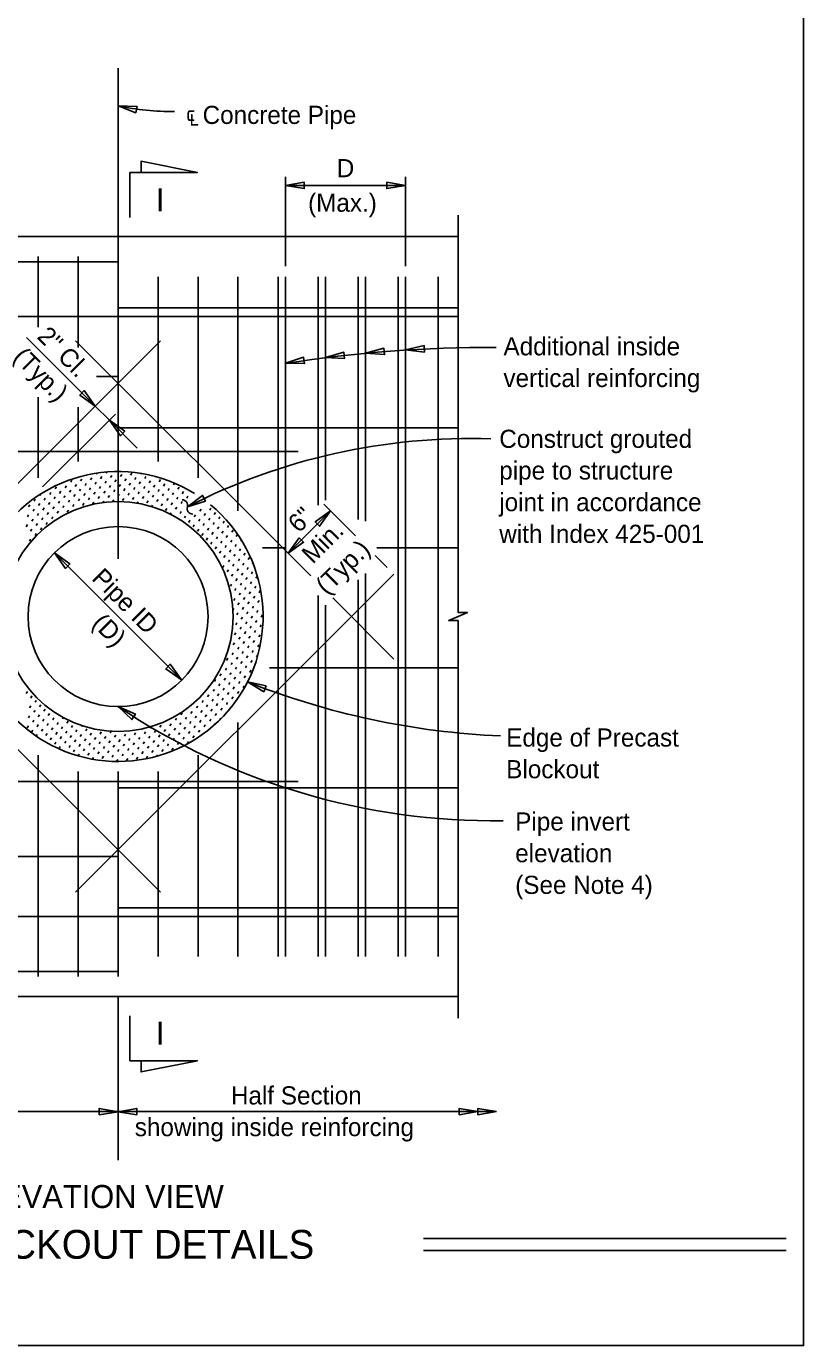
# Model space of a CAD drawing. Extents: x 0 to 30.8, y 0 to 19.8.
# Drawn here: x 24.32 to 30.8, y 0 to 11 of the extents above; entities that cross this region are included whole.
import ezdxf

# ---------------------------------------------------------------- set-up
doc = ezdxf.new("R2010")
doc.units = 0
for name, color, linetype in [('CL_Major', 7, 'Continuous'), ('Dimension', 7, 'Continuous'), ('Miscellaneous', 7, 'Continuous'), ('Miscellaneous1', 7, 'Continuous'), ('Rebar', 7, 'Continuous'), ('SubStrConc', 7, 'Continuous'), ('SubStrConc_h', 7, 'Continuous'), ('TextStructures', 7, 'Continuous')]:
    doc.layers.add(name, color=color, linetype=linetype)

msp = doc.modelspace()

# ---------------------------------------------------------------- linework, layer by layer
at = {"layer": 'CL_Major'}
for p, q in [((25.088, 10.648), (25.088, 6.558)), ((25.088, 4.785), (25.088, 4.383)), ((25.088, 1.547), (25.088, 2.91))]:
    msp.add_line(p, q, dxfattribs=at)
at = {"layer": 'Dimension'}
for p, q in [((25.749, 9.779), (25.28, 9.872)), ((25.28, 9.872), (25.28, 9.779)), ((25.186, 9.404), (25.186, 9.779)), ((25.186, 9.779), (25.749, 9.779)), ((26.483, 8.997), (26.483, 9.743)), ((27.483, 8.997), (27.483, 9.743)), ((26.483, 9.671), (27.483, 9.671)), ((24.324, 8.404), (24.897, 7.831)), ((25.015, 7.713), (24.897, 7.831)), ((24.459, 7.157), (25.067, 7.765)), ((25.015, 7.713), (25.248, 7.48)), ((26.858, 6.958), (26.505, 6.604)), ((27.065, 6.751), (26.801, 7.015)), ((25.615, 5.55), (24.557, 6.607)), ((27.329, 6.487), (27.23, 6.587)), ((25.186, 2.75), (25.186, 2.375)), ((25.186, 2.375), (25.749, 2.375)), ((25.749, 2.375), (25.28, 2.282)), ((25.28, 2.282), (25.28, 2.375)), ((25.088, 1.951), (21.845, 1.951)), ((25.088, 1.951), (28.242, 1.951)), ((30.655, 0.894), (27.633, 0.894)), ((30.655, 0.794), (27.633, 0.794))]:
    msp.add_line(p, q, dxfattribs=at)
for points in [[(25.088, 10.334), (25.235, 10.276), (25.246, 10.328)], [(25.28, 9.779), (25.28, 9.872), (25.749, 9.779)], [(26.483, 9.671), (26.639, 9.644), (26.639, 9.697)], [(27.483, 9.671), (27.327, 9.697), (27.327, 9.644)], [(26.817, 8.235), (26.968, 8.281), (26.975, 8.229)], [(27.15, 8.272), (27.303, 8.313), (27.308, 8.261)], [(27.483, 8.299), (27.637, 8.335), (27.641, 8.282)], [(26.483, 8.188), (26.633, 8.239), (26.642, 8.186)], [(24.897, 7.831), (24.806, 7.96), (24.768, 7.923)], [(25.015, 7.713), (25.107, 7.584), (25.144, 7.622)], [(25.665, 6.991), (25.816, 7.039), (25.792, 7.086)], [(26.858, 6.958), (26.729, 6.866), (26.767, 6.829)], [(26.505, 6.604), (26.634, 6.696), (26.597, 6.733)], [(24.557, 6.607), (24.649, 6.478), (24.686, 6.516)], [(25.615, 5.55), (25.523, 5.679), (25.486, 5.641)], [(26.166, 5.532), (26.301, 5.45), (26.321, 5.499)], [(25.088, 5.327), (25.203, 5.218), (25.232, 5.262)], [(25.28, 2.375), (25.28, 2.282), (25.749, 2.375)], [(25.088, 1.95), (24.931, 1.977), (24.931, 1.924)], [(25.088, 1.95), (25.244, 1.924), (25.244, 1.977)], [(28.086, 1.951), (27.93, 1.977), (27.93, 1.924)], [(28.242, 1.951), (28.086, 1.977), (28.086, 1.924)]]:
    msp.add_lwpolyline(points, close=True, dxfattribs=at)
msp.add_lwpolyline([(27.921, 2.73), (27.921, 6.043), (27.843, 6.043), (27.921, 6.077), (27.998, 6.111), (27.921, 6.111), (27.921, 9.424)], dxfattribs=at)
for centre, radius, start, end in [((25.551, 12.543), 2.257, 258.1436, 270.1956), ((28.171, -2.483), 10.803, 89.6404, 98.9861), ((28.024, 2.388), 5.173, 88.1103, 117.1325), ((25.623, 7.005), 0.0447, 341.3118, 93.039), ((25.708, 6.976), 0.0447, 161.3118, 273.039), ((28.551, 11.535), 6.459, 248.3277, 267.5443), ((28.22, 10.004), 5.63, 236.1859, 270.7687)]:
    msp.add_arc(centre, radius, start, end, dxfattribs=at)
at = {"layer": 'Miscellaneous'}
for p, q in [((24.906, 7.263), (24.911, 7.272)), ((24.989, 7.272), (24.994, 7.281)), ((25.072, 7.282), (25.073, 7.285)), ((25.108, 7.245), (25.118, 7.262)), ((25.191, 7.255), (25.201, 7.272)), ((25.274, 7.265), (25.277, 7.27)), ((24.564, 7.141), (24.574, 7.158)), ((24.647, 7.151), (24.657, 7.167)), ((24.693, 7.197), (24.703, 7.214)), ((24.73, 7.16), (24.74, 7.177)), ((24.776, 7.207), (24.786, 7.223)), ((24.813, 7.17), (24.823, 7.187)), ((24.823, 7.253), (24.824, 7.256)), ((24.849, 7.133), (24.859, 7.15)), ((24.859, 7.216), (24.869, 7.233)), ((24.896, 7.18), (24.906, 7.196)), ((24.932, 7.143), (24.942, 7.16)), ((24.942, 7.226), (24.952, 7.243)), ((24.979, 7.189), (24.989, 7.206)), ((25.015, 7.153), (25.025, 7.17)), ((25.025, 7.236), (25.035, 7.253)), ((25.062, 7.199), (25.072, 7.216)), ((25.098, 7.162), (25.108, 7.179)), ((25.145, 7.209), (25.154, 7.226)), ((25.181, 7.172), (25.191, 7.189)), ((25.218, 7.136), (25.228, 7.152)), ((25.228, 7.219), (25.237, 7.235)), ((25.264, 7.182), (25.274, 7.199)), ((25.301, 7.145), (25.311, 7.162)), ((25.311, 7.228), (25.32, 7.245)), ((25.347, 7.192), (25.357, 7.208)), ((25.384, 7.155), (25.394, 7.172)), ((25.394, 7.238), (25.398, 7.245)), ((25.43, 7.201), (25.44, 7.218)), ((25.467, 7.165), (25.477, 7.182)), ((25.55, 7.174), (25.559, 7.19)), ((25.587, 7.138), (25.596, 7.155)), ((24.388, 7.038), (24.398, 7.055)), ((24.435, 7.085), (24.443, 7.099)), ((24.471, 7.048), (24.481, 7.065)), ((24.518, 7.094), (24.527, 7.111)), ((24.554, 7.058), (24.564, 7.075)), ((24.591, 7.021), (24.601, 7.038)), ((24.601, 7.104), (24.61, 7.121)), ((24.637, 7.068), (24.647, 7.084)), ((24.674, 7.031), (24.684, 7.048)), ((24.684, 7.114), (24.693, 7.131)), ((24.72, 7.077), (24.73, 7.094)), ((24.757, 7.041), (24.767, 7.057)), ((24.767, 7.124), (24.776, 7.14)), ((24.803, 7.087), (24.813, 7.104)), ((24.84, 7.05), (24.849, 7.067)), ((24.886, 7.097), (24.896, 7.113)), ((24.923, 7.06), (24.932, 7.077)), ((24.961, 7.026), (24.969, 7.04)), ((24.969, 7.106), (24.979, 7.123)), ((25.006, 7.07), (25.015, 7.087)), ((25.042, 7.033), (25.052, 7.05)), ((25.052, 7.116), (25.062, 7.133)), ((25.089, 7.08), (25.098, 7.096)), ((25.125, 7.043), (25.135, 7.06)), ((25.135, 7.126), (25.145, 7.143)), ((25.172, 7.089), (25.181, 7.106)), ((25.208, 7.053), (25.218, 7.069)), ((25.255, 7.099), (25.264, 7.116)), ((25.291, 7.062), (25.301, 7.079)), ((25.328, 7.026), (25.338, 7.042)), ((25.338, 7.109), (25.347, 7.125)), ((25.374, 7.072), (25.384, 7.089)), ((25.411, 7.035), (25.421, 7.052)), ((25.421, 7.118), (25.43, 7.135)), ((25.457, 7.082), (25.467, 7.099)), ((25.494, 7.045), (25.504, 7.062)), ((25.504, 7.128), (25.513, 7.145)), ((25.54, 7.091), (25.55, 7.108)), ((25.577, 7.055), (25.587, 7.072)), ((25.623, 7.101), (25.633, 7.118)), ((25.66, 7.065), (25.67, 7.081)), ((25.706, 7.111), (25.708, 7.114)), ((24.342, 6.992), (24.352, 7.009)), ((24.379, 6.955), (24.388, 6.972)), ((24.415, 6.919), (24.425, 6.936)), ((24.425, 7.002), (24.435, 7.019)), ((24.461, 6.965), (24.471, 6.982)), ((24.498, 6.928), (24.508, 6.945)), ((24.508, 7.011), (24.518, 7.028)), ((24.544, 6.975), (24.554, 6.992)), ((24.581, 6.938), (24.591, 6.955)), ((24.627, 6.985), (24.637, 7.001)), ((24.664, 6.948), (24.674, 6.965)), ((24.71, 6.994), (24.72, 7.011)), ((24.793, 7.004), (24.803, 7.021)), ((24.876, 7.014), (24.886, 7.031)), ((25.248, 7.021), (25.255, 7.033)), ((25.367, 6.993), (25.374, 7.006)), ((25.448, 6.999), (25.457, 7.016)), ((25.484, 6.962), (25.494, 6.979)), ((25.523, 6.929), (25.531, 6.942)), ((25.531, 7.009), (25.54, 7.025)), ((25.567, 6.972), (25.577, 6.989)), ((25.604, 6.935), (25.613, 6.952)), ((25.613, 7.018), (25.623, 7.035)), ((25.77, 6.955), (25.779, 6.972)), ((25.806, 6.918), (25.816, 6.935)), ((25.853, 6.964), (25.862, 6.981)), ((25.889, 6.928), (25.899, 6.945)), ((24.322, 6.826), (24.332, 6.843)), ((24.332, 6.909), (24.342, 6.926)), ((24.369, 6.872), (24.379, 6.889)), ((24.405, 6.836), (24.415, 6.853)), ((24.452, 6.882), (24.461, 6.899)), ((24.488, 6.845), (24.498, 6.862)), ((24.535, 6.892), (24.544, 6.909)), ((24.626, 6.916), (24.627, 6.918)), ((25.64, 6.899), (25.65, 6.915)), ((25.677, 6.862), (25.687, 6.879)), ((25.714, 6.825), (25.723, 6.842)), ((25.723, 6.908), (25.733, 6.925)), ((25.76, 6.872), (25.77, 6.889)), ((25.797, 6.835), (25.806, 6.852)), ((25.843, 6.881), (25.853, 6.898)), ((25.88, 6.845), (25.889, 6.862)), ((25.916, 6.808), (25.926, 6.825)), ((25.926, 6.891), (25.936, 6.908)), ((25.963, 6.855), (25.972, 6.871)), ((25.999, 6.818), (26.009, 6.835)), ((24.349, 6.706), (24.359, 6.723)), ((24.359, 6.789), (24.369, 6.806)), ((24.396, 6.753), (24.405, 6.77)), ((24.442, 6.799), (24.452, 6.816)), ((25.75, 6.789), (25.76, 6.806)), ((25.787, 6.752), (25.797, 6.769)), ((25.824, 6.715), (25.833, 6.732)), ((25.833, 6.798), (25.843, 6.815)), ((25.87, 6.762), (25.88, 6.779)), ((25.907, 6.725), (25.916, 6.742)), ((25.953, 6.772), (25.963, 6.788)), ((25.989, 6.735), (25.999, 6.752)), ((26.026, 6.698), (26.036, 6.715)), ((26.036, 6.781), (26.046, 6.798)), ((26.072, 6.745), (26.082, 6.761)), ((26.109, 6.708), (26.113, 6.715)), ((25.86, 6.679), (25.87, 6.696)), ((25.897, 6.642), (25.907, 6.659)), ((25.933, 6.606), (25.943, 6.622)), ((25.943, 6.689), (25.953, 6.705)), ((25.98, 6.652), (25.989, 6.669)), ((26.016, 6.615), (26.026, 6.632)), ((26.063, 6.662), (26.072, 6.678)), ((26.099, 6.625), (26.109, 6.642)), ((26.136, 6.588), (26.146, 6.605)), ((25.929, 6.533), (25.933, 6.539)), ((25.96, 6.486), (25.97, 6.503)), ((25.97, 6.569), (25.98, 6.586)), ((26.007, 6.532), (26.016, 6.549)), ((26.043, 6.496), (26.053, 6.513)), ((26.053, 6.579), (26.063, 6.595)), ((26.09, 6.542), (26.099, 6.559)), ((26.126, 6.505), (26.136, 6.522)), ((26.173, 6.552), (26.182, 6.569)), ((26.209, 6.515), (26.212, 6.519)), ((25.996, 6.381), (25.997, 6.383)), ((25.997, 6.449), (26.007, 6.466)), ((26.034, 6.413), (26.043, 6.43)), ((26.07, 6.376), (26.08, 6.393)), ((26.08, 6.459), (26.09, 6.476)), ((26.117, 6.422), (26.126, 6.439)), ((26.153, 6.386), (26.163, 6.403)), ((26.163, 6.469), (26.173, 6.486)), ((26.2, 6.432), (26.209, 6.449)), ((26.236, 6.396), (26.246, 6.412)), ((26.024, 6.33), (26.034, 6.347)), ((26.06, 6.293), (26.07, 6.31)), ((26.097, 6.257), (26.107, 6.273)), ((26.107, 6.339), (26.117, 6.356)), ((26.143, 6.303), (26.153, 6.32)), ((26.18, 6.266), (26.19, 6.283)), ((26.19, 6.349), (26.2, 6.366)), ((26.226, 6.313), (26.236, 6.329)), ((26.263, 6.276), (26.273, 6.293)), ((26.051, 6.21), (26.06, 6.227)), ((26.087, 6.174), (26.097, 6.19)), ((26.134, 6.22), (26.143, 6.237)), ((26.17, 6.183), (26.18, 6.2)), ((26.207, 6.147), (26.217, 6.163)), ((26.217, 6.23), (26.226, 6.246)), ((26.253, 6.193), (26.263, 6.21)), ((26.29, 6.156), (26.293, 6.161)), ((26.043, 6.131), (26.051, 6.144)), ((26.078, 6.091), (26.087, 6.107)), ((26.114, 6.054), (26.124, 6.071)), ((26.124, 6.137), (26.134, 6.154)), ((26.161, 6.1), (26.17, 6.117)), ((26.197, 6.064), (26.207, 6.08)), ((26.244, 6.11), (26.253, 6.127)), ((26.28, 6.073), (26.29, 6.09)), ((26.058, 5.925), (26.068, 5.941)), ((26.068, 6.008), (26.078, 6.024)), ((26.105, 5.971), (26.114, 5.988)), ((26.141, 5.934), (26.151, 5.951)), ((26.151, 6.017), (26.161, 6.034)), ((26.188, 5.981), (26.197, 5.997)), ((26.224, 5.944), (26.234, 5.961)), ((26.234, 6.027), (26.244, 6.044)), ((26.271, 5.99), (26.28, 6.007)), ((26.048, 5.842), (26.058, 5.858)), ((26.095, 5.888), (26.105, 5.905)), ((26.131, 5.851), (26.141, 5.868)), ((26.168, 5.815), (26.178, 5.832)), ((26.178, 5.898), (26.188, 5.914)), ((26.214, 5.861), (26.224, 5.878)), ((26.251, 5.824), (26.261, 5.841)), ((26.261, 5.907), (26.271, 5.924)), ((25.992, 5.712), (26.002, 5.729)), ((26.003, 5.797), (26.012, 5.812)), ((26.039, 5.759), (26.048, 5.775)), ((26.075, 5.722), (26.085, 5.739)), ((26.085, 5.805), (26.095, 5.822)), ((26.122, 5.768), (26.131, 5.785)), ((26.158, 5.732), (26.168, 5.749)), ((26.205, 5.778), (26.214, 5.795)), ((26.241, 5.741), (26.251, 5.758)), ((25.983, 5.629), (25.992, 5.646)), ((26.019, 5.593), (26.029, 5.609)), ((26.029, 5.676), (26.039, 5.692)), ((26.066, 5.639), (26.075, 5.656)), ((26.102, 5.602), (26.112, 5.619)), ((26.112, 5.685), (26.122, 5.702)), ((26.149, 5.649), (26.158, 5.666)), ((26.185, 5.612), (26.195, 5.629)), ((26.195, 5.695), (26.205, 5.712)), ((25.89, 5.537), (25.9, 5.553)), ((25.927, 5.5), (25.936, 5.517)), ((25.936, 5.583), (25.946, 5.6)), ((25.973, 5.546), (25.983, 5.563)), ((26.01, 5.51), (26.019, 5.526)), ((26.056, 5.556), (26.066, 5.573)), ((26.093, 5.519), (26.102, 5.536)), ((26.129, 5.483), (26.139, 5.5)), ((26.139, 5.566), (26.149, 5.583)), ((24.323, 5.435), (24.333, 5.452)), ((24.36, 5.398), (24.369, 5.415)), ((25.834, 5.407), (25.844, 5.424)), ((25.88, 5.454), (25.89, 5.47)), ((25.917, 5.417), (25.927, 5.434)), ((25.954, 5.38), (25.963, 5.397)), ((25.963, 5.463), (25.973, 5.48)), ((26, 5.427), (26.01, 5.444)), ((26.037, 5.39), (26.046, 5.407)), ((26.046, 5.473), (26.056, 5.49)), ((26.083, 5.436), (26.093, 5.453)), ((24.35, 5.315), (24.36, 5.332)), ((24.387, 5.279), (24.396, 5.295)), ((24.396, 5.362), (24.406, 5.378)), ((24.433, 5.325), (24.443, 5.342)), ((24.47, 5.288), (24.479, 5.305)), ((25.658, 5.305), (25.661, 5.31)), ((25.695, 5.268), (25.705, 5.285)), ((25.741, 5.315), (25.751, 5.331)), ((25.778, 5.278), (25.788, 5.295)), ((25.788, 5.361), (25.797, 5.378)), ((25.824, 5.324), (25.834, 5.341)), ((25.861, 5.288), (25.871, 5.304)), ((25.871, 5.371), (25.88, 5.387)), ((25.907, 5.334), (25.917, 5.351)), ((25.944, 5.297), (25.954, 5.314)), ((25.99, 5.344), (26, 5.361)), ((24.34, 5.232), (24.35, 5.249)), ((24.377, 5.196), (24.387, 5.212)), ((24.414, 5.159), (24.423, 5.176)), ((24.423, 5.242), (24.433, 5.259)), ((24.46, 5.205), (24.47, 5.222)), ((24.497, 5.169), (24.506, 5.186)), ((24.506, 5.252), (24.516, 5.269)), ((24.543, 5.215), (24.553, 5.232)), ((24.58, 5.178), (24.589, 5.195)), ((24.626, 5.225), (24.632, 5.235)), ((24.662, 5.188), (24.672, 5.205)), ((24.699, 5.152), (24.709, 5.168)), ((25.436, 5.156), (25.446, 5.173)), ((25.483, 5.202), (25.484, 5.205)), ((25.519, 5.166), (25.529, 5.183)), ((25.566, 5.212), (25.575, 5.229)), ((25.602, 5.176), (25.612, 5.192)), ((25.612, 5.259), (25.622, 5.275)), ((25.649, 5.222), (25.658, 5.239)), ((25.685, 5.185), (25.695, 5.202)), ((25.731, 5.232), (25.741, 5.248)), ((25.768, 5.195), (25.778, 5.212)), ((25.805, 5.158), (25.814, 5.175)), ((25.814, 5.241), (25.824, 5.258)), ((25.851, 5.205), (25.861, 5.221)), ((25.892, 5.176), (25.897, 5.185)), ((25.897, 5.251), (25.907, 5.268)), ((25.935, 5.216), (25.944, 5.231)), ((25.984, 5.267), (25.99, 5.278)), ((24.331, 5.149), (24.34, 5.166)), ((24.367, 5.113), (24.377, 5.129)), ((24.406, 5.08), (24.414, 5.093)), ((24.45, 5.122), (24.46, 5.139)), ((24.487, 5.086), (24.497, 5.103)), ((24.523, 5.049), (24.533, 5.066)), ((24.533, 5.132), (24.543, 5.149)), ((24.57, 5.095), (24.58, 5.112)), ((24.606, 5.059), (24.616, 5.076)), ((24.616, 5.142), (24.626, 5.159)), ((24.653, 5.105), (24.662, 5.122)), ((24.689, 5.069), (24.699, 5.085)), ((24.736, 5.115), (24.745, 5.132)), ((24.772, 5.078), (24.782, 5.095)), ((24.782, 5.161), (24.786, 5.168)), ((24.809, 5.042), (24.819, 5.058)), ((24.819, 5.125), (24.828, 5.141)), ((24.855, 5.088), (24.865, 5.105)), ((24.892, 5.051), (24.902, 5.068)), ((24.902, 5.134), (24.903, 5.137)), ((24.938, 5.098), (24.948, 5.115)), ((24.975, 5.061), (24.985, 5.078)), ((25.021, 5.107), (25.03, 5.122)), ((25.058, 5.071), (25.068, 5.088)), ((25.104, 5.117), (25.106, 5.12)), ((25.141, 5.081), (25.151, 5.097)), ((25.178, 5.044), (25.187, 5.061)), ((25.224, 5.09), (25.234, 5.107)), ((25.261, 5.054), (25.27, 5.07)), ((25.27, 5.137), (25.27, 5.137)), ((25.307, 5.1), (25.317, 5.117)), ((25.344, 5.063), (25.353, 5.08)), ((25.353, 5.146), (25.361, 5.159)), ((25.39, 5.11), (25.4, 5.127)), ((25.426, 5.073), (25.436, 5.09)), ((25.473, 5.119), (25.483, 5.136)), ((25.509, 5.083), (25.519, 5.1)), ((25.546, 5.046), (25.556, 5.063)), ((25.556, 5.129), (25.566, 5.146)), ((25.592, 5.093), (25.602, 5.109)), ((25.629, 5.056), (25.639, 5.073)), ((25.639, 5.139), (25.649, 5.156)), ((25.675, 5.102), (25.685, 5.119)), ((25.712, 5.066), (25.722, 5.082)), ((25.722, 5.149), (25.731, 5.165)), ((25.758, 5.112), (25.768, 5.129)), ((24.448, 5.052), (24.45, 5.056)), ((24.56, 5.012), (24.57, 5.029)), ((24.597, 4.976), (24.606, 4.993)), ((24.642, 4.954), (24.643, 4.956)), ((24.643, 5.022), (24.653, 5.039)), ((24.68, 4.986), (24.689, 5.002)), ((24.716, 4.949), (24.726, 4.966)), ((24.726, 5.032), (24.736, 5.049)), ((24.763, 4.995), (24.772, 5.012)), ((24.799, 4.959), (24.809, 4.975)), ((24.846, 5.005), (24.855, 5.022)), ((24.882, 4.968), (24.892, 4.985)), ((24.919, 4.932), (24.929, 4.949)), ((24.929, 5.015), (24.938, 5.032)), ((24.965, 4.978), (24.975, 4.995)), ((25.002, 4.942), (25.012, 4.958)), ((25.012, 5.024), (25.021, 5.041)), ((25.048, 4.988), (25.058, 5.005)), ((25.085, 4.951), (25.095, 4.968)), ((25.095, 5.034), (25.104, 5.051)), ((25.131, 4.998), (25.141, 5.014)), ((25.168, 4.961), (25.178, 4.978)), ((25.214, 5.007), (25.224, 5.024)), ((25.251, 4.971), (25.261, 4.987)), ((25.287, 4.934), (25.297, 4.951)), ((25.297, 5.017), (25.307, 5.034)), ((25.334, 4.98), (25.344, 4.997)), ((25.37, 4.944), (25.38, 4.961)), ((25.38, 5.027), (25.39, 5.044)), ((25.417, 4.99), (25.426, 5.007)), ((25.453, 4.953), (25.463, 4.97)), ((25.463, 5.036), (25.473, 5.053)), ((25.5, 5), (25.509, 5.017)), ((25.536, 4.963), (25.546, 4.98)), ((25.583, 5.01), (25.592, 5.026)), ((25.666, 5.019), (25.675, 5.036)), ((24.755, 4.916), (24.763, 4.929)), ((24.836, 4.922), (24.846, 4.939)), ((24.874, 4.888), (24.882, 4.902)), ((24.956, 4.895), (24.965, 4.912)), ((25, 4.872), (25.002, 4.875)), ((25.038, 4.905), (25.048, 4.922)), ((25.076, 4.869), (25.085, 4.885)), ((25.121, 4.915), (25.131, 4.931)), ((25.158, 4.878), (25.168, 4.895)), ((25.204, 4.924), (25.214, 4.941)), ((25.241, 4.888), (25.251, 4.904)), ((25.324, 4.897), (25.334, 4.914)), ((25.41, 4.913), (25.417, 4.924))]:
    msp.add_line(p, q, dxfattribs=at)
at = {"layer": 'Miscellaneous1'}
msp.add_lwpolyline([(0, 19.8), (30.8, 19.8), (30.8, 0), (0, 0)], close=True, dxfattribs=at)
at = {"layer": 'Rebar'}
for p, q in [((22.254, 9.035), (25.088, 9.035)), ((24.421, 9.077), (24.421, 8.489)), ((24.754, 9.077), (24.754, 8.32)), ((25.088, 9.077), (25.088, 7.739)), ((25.421, 8.91), (25.421, 7.368)), ((25.754, 8.91), (25.754, 7.232)), ((26.087, 8.91), (26.087, 6.959)), ((26.421, 8.91), (26.421, 3.244)), ((26.483, 8.91), (26.483, 3.244)), ((26.754, 8.91), (26.754, 7.005)), ((26.817, 8.91), (26.817, 7.048)), ((27.087, 8.91), (27.087, 6.885)), ((27.15, 8.91), (27.15, 6.871)), ((27.421, 8.91), (27.421, 3.244)), ((27.483, 8.91), (27.483, 3.244)), ((27.754, 8.91), (27.754, 3.244)), ((25.088, 8.649), (27.921, 8.649)), ((25.441, 8.375), (22.789, 5.723)), ((24.734, 8.375), (26.694, 6.415)), ((24.908, 8.077), (25.088, 8.077)), ((24.421, 7.905), (24.421, 7.232)), ((24.754, 7.823), (24.754, 7.368)), ((25.088, 7.649), (27.921, 7.649)), ((25.088, 7.542), (25.088, 7.41)), ((23.588, 7.452), (26.588, 7.452)), ((26.292, 6.649), (26.483, 6.649)), ((27.243, 6.649), (27.921, 6.649)), ((25.441, 3.779), (22.789, 6.431)), ((24.734, 3.779), (27.386, 6.431)), ((27.087, 6.382), (27.087, 3.244)), ((27.15, 6.436), (27.15, 3.244)), ((26.754, 6.253), (26.754, 3.244)), ((26.817, 6.171), (26.817, 3.244)), ((26.876, 6.233), (27.386, 5.723)), ((26.35, 5.649), (27.921, 5.649)), ((26.087, 5.195), (26.087, 3.244)), ((24.421, 4.922), (24.421, 3.077)), ((25.754, 4.922), (25.754, 3.244)), ((24.754, 4.786), (24.754, 3.077)), ((25.088, 4.744), (25.088, 3.077)), ((25.421, 4.786), (25.421, 3.244)), ((23.588, 4.702), (26.588, 4.702)), ((25.088, 4.649), (27.921, 4.649)), ((22.254, 4.077), (25.088, 4.077)), ((25.088, 3.649), (27.921, 3.649)), ((22.254, 3.119), (25.088, 3.119))]:
    msp.add_line(p, q, dxfattribs=at)
at = {"layer": 'SubStrConc'}
for p, q in [((22.254, 9.244), (27.921, 9.244)), ((22.254, 2.91), (27.921, 2.91))]:
    msp.add_line(p, q, dxfattribs=at)
msp.add_circle((25.088, 6.077), 0.75, dxfattribs=at)
msp.add_arc((25.088, 6.077), 1.208, 58.2129, 50.3979, dxfattribs=at)
at = {"layer": 'SubStrConc_h'}
for p, q in [((22.254, 8.577), (27.921, 8.577)), ((22.254, 3.577), (27.921, 3.577))]:
    msp.add_line(p, q, dxfattribs=at)
msp.add_circle((25.088, 6.077), 0.958, dxfattribs=at)
at = {"layer": 'TextStructures'}
msp.add_lwpolyline([(0, 19.477), (30.8, 19.477), (30.8, 0), (0, 0)], close=True, dxfattribs=at)

# ---------------------------------------------------------------- texts
at = {"layer": 'Dimension'}
for s, rotation, p in [('2" Cl.', 315, (24.405, 8.403)), ('(Typ.)', 315, (24.205, 8.229)), ('6"', 45, (26.595, 6.767)), ('Min.', 45, (26.71, 6.509)), ('(Typ.)', 45, (26.826, 6.251)), ('Pipe ID', 315, (24.86, 6.387)), ('(D)', 315, (24.863, 6.011))]:
    msp.add_text(s, height=0.1512, rotation=rotation, dxfattribs=at).set_placement(p)
for s, p in [('Additional inside', (28.299, 8.254)), ('vertical reinforcing', (28.299, 7.99)), ('Construct grouted', (28.264, 7.483)), ('pipe to structure', (28.264, 7.219)), ('joint in accordance', (28.264, 6.955)), ('with Index 425-001', (28.264, 6.691)), ('Edge of Precast', (28.322, 4.993)), ('Blockout', (28.322, 4.729)), ('Pipe invert', (28.397, 4.293)), ('elevation', (28.397, 4.029)), ('(See Note 4)', (28.397, 3.765)), ('Half Section', (26.028, 2.01)), ('showing inside reinforcing', (25.227, 1.746))]:
    msp.add_text(s, height=0.1512, dxfattribs=at).set_placement(p)
at = {"layer": 'TextStructures'}
for s, height, p in [('℄ Concrete Pipe', 0.1512, (25.654, 10.183)), ('D', 0.151, (26.91, 9.739)), ('I', 0.192, (25.402, 9.454)), ('(Max.)', 0.1512, (26.671, 9.451)), ('I', 0.192, (25.402, 2.508)), ('ELEVATION VIEW', 0.192, (23.8, 1.147)), ('PIPE BLOCKOUT DETAILS', 0.24, (22.71, 0.724))]:
    msp.add_text(s, height=height, dxfattribs=at).set_placement(p)

doc.saveas('drawing.dxf')
